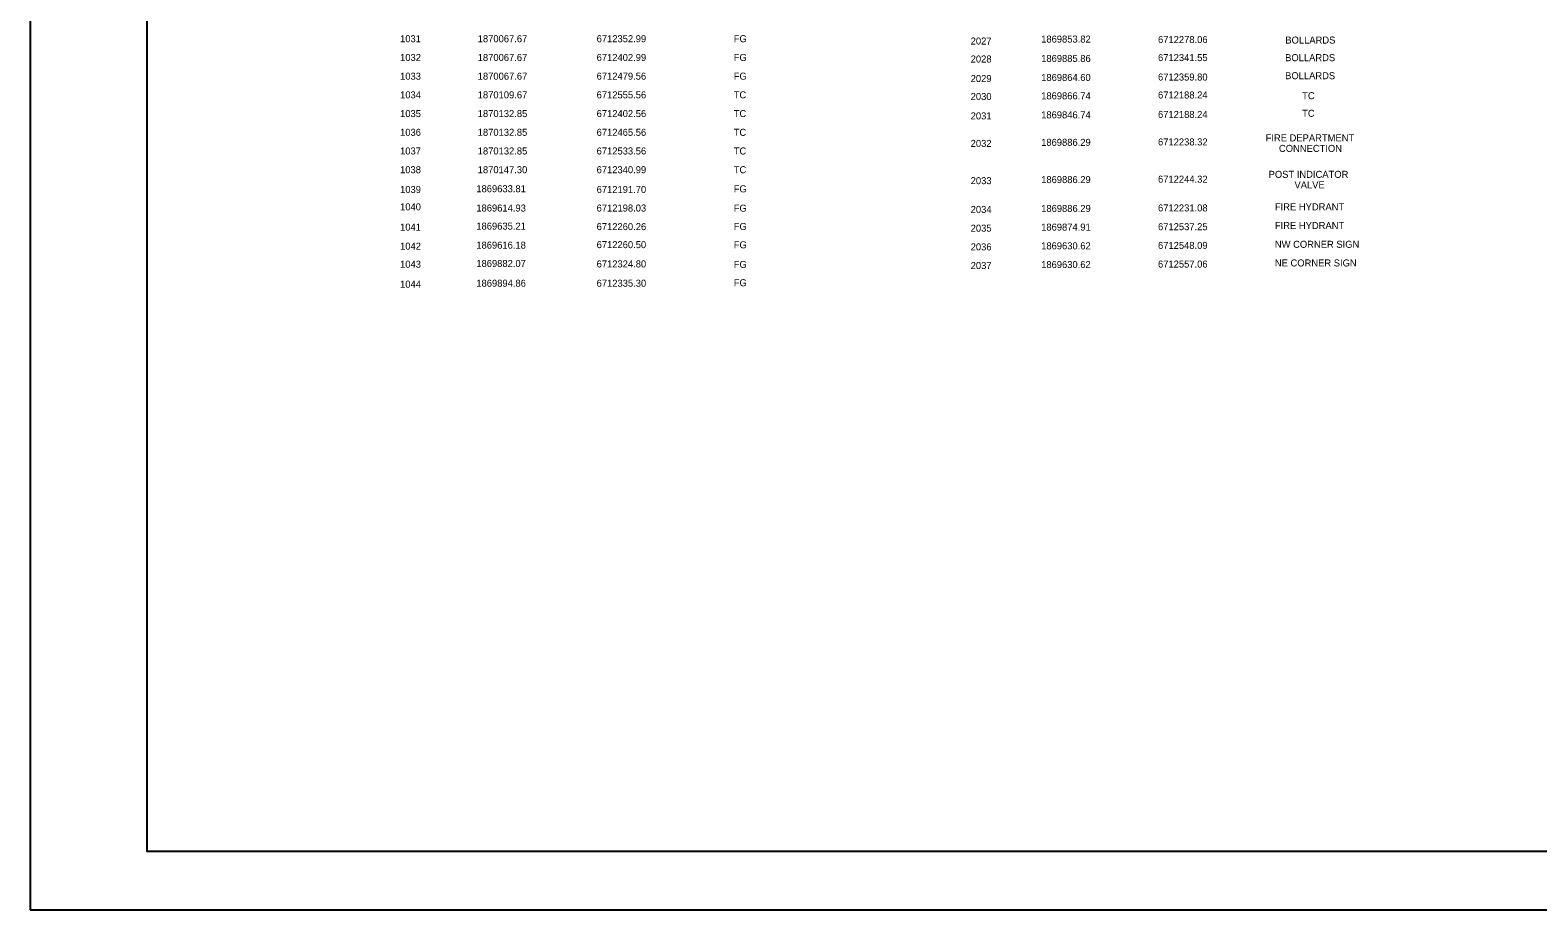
# Model space of a CAD drawing. Extents: x 0 to 4.36, y 0 to 2.5.
# Drawn here: x 0 to 2.15, y 0 to 1.254 of the extents above; entities that cross this region are included whole.
import ezdxf

# ---------------------------------------------------------------- set-up
doc = ezdxf.new("R2010")
doc.units = 0
for name, color, linetype in [('C-TEXT', 7, 'Continuous'), ('G-TTLB-OTLN', 7, 'Continuous'), ('G-TTLB-VIEW', 7, 'Continuous')]:
    doc.layers.add(name, color=color, linetype=linetype)

msp = doc.modelspace()

# ---------------------------------------------------------------- linework, layer by layer
at = {"layer": 'G-TTLB-OTLN'}
msp.add_lwpolyline([(0, 0), (3.5, 0), (3.5, 2.5), (0, 2.5)], close=True, dxfattribs=at)
at = {"layer": 'G-TTLB-VIEW'}
msp.add_lwpolyline([(0.1667, 2.4167), (3.0729, 2.4167), (3.0729, 0.0833), (0.1667, 0.0833)], close=True, dxfattribs=at)

# ---------------------------------------------------------------- texts
at = {"layer": 'C-TEXT'}
for s, p in [('1031', (0.5274, 1.2366)), ('1870067.67', (0.6381, 1.2366)), ('6712352.99', (0.8076, 1.2366)), ('FG', (1.0031, 1.2366)), ('2027', (1.3409, 1.2333)), ('1869853.82', (1.4414, 1.2361)), ('6712278.06', (1.608, 1.2354)), ('BOLLARDS', (1.7895, 1.2347)), ('1032', (0.5274, 1.2099)), ('1870067.67', (0.6381, 1.2099)), ('6712402.99', (0.8076, 1.2099)), ('FG', (1.0031, 1.2099)), ('2028', (1.3409, 1.2077)), ('1869885.86', (1.4414, 1.2085)), ('6712341.55', (1.608, 1.2097)), ('BOLLARDS', (1.7892, 1.2096)), ('1033', (0.5274, 1.1832)), ('1870067.67', (0.6381, 1.1832)), ('6712479.56', (0.8076, 1.1832)), ('FG', (1.0031, 1.1832)), ('2029', (1.3409, 1.1799)), ('1869864.60', (1.4414, 1.1814)), ('6712359.80', (1.608, 1.182)), ('BOLLARDS', (1.7892, 1.1839)), ('1034', (0.5274, 1.1566)), ('1870109.67', (0.6381, 1.1566)), ('6712555.56', (0.8076, 1.1566)), ('TC', (1.0031, 1.1566)), ('2030', (1.3409, 1.1543)), ('1869866.74', (1.4414, 1.1552)), ('6712188.24', (1.608, 1.1564)), ('TC', (1.8135, 1.1554)), ('1035', (0.5274, 1.1299)), ('1870132.85', (0.6381, 1.1299)), ('6712402.56', (0.8076, 1.1299)), ('TC', (1.0031, 1.1299)), ('TC', (1.8135, 1.1303)), ('2031', (1.3409, 1.1266)), ('1869846.74', (1.4414, 1.1281)), ('6712188.24', (1.608, 1.1287)), ('1036', (0.5274, 1.1032)), ('1870132.85', (0.6381, 1.1032)), ('6712465.56', (0.8076, 1.1032)), ('TC', (1.0031, 1.1032)), ('2032', (1.3409, 1.0874)), ('1869886.29', (1.4414, 1.0889)), ('6712238.32', (1.608, 1.0895)), ('FIRE DEPARTMENT', (1.7614, 1.0953)), ('1037', (0.5274, 1.0766)), ('1870132.85', (0.6381, 1.0766)), ('6712533.56', (0.8076, 1.0766)), ('TC', (1.0031, 1.0766)), ('CONNECTION', (1.7804, 1.0803)), ('1038', (0.5274, 1.0499)), ('1870147.30', (0.6381, 1.0499)), ('6712340.99', (0.8076, 1.0499)), ('TC', (1.0031, 1.0499)), ('POST INDICATOR', (1.7657, 1.0433)), ('1039', (0.5274, 1.0217)), ('1869633.81', (0.6361, 1.0228)), ('6712191.70', (0.8076, 1.0217)), ('FG', (1.0031, 1.0226)), ('2033', (1.3409, 1.0343)), ('1869886.29', (1.4414, 1.0358)), ('6712244.32', (1.608, 1.0364)), ('VALVE', (1.8025, 1.0283)), ('1040', (0.5274, 0.997)), ('1869614.93', (0.6361, 0.9953)), ('6712198.03', (0.8076, 0.9953)), ('FG', (1.0031, 0.9951)), ('2034', (1.3409, 0.9933)), ('1869886.29', (1.4414, 0.9947)), ('6712231.08', (1.608, 0.9954)), ('FIRE HYDRANT', (1.7746, 0.997)), ('1041', (0.5274, 0.9681)), ('1869635.21', (0.6361, 0.9695)), ('6712260.26', (0.8076, 0.9688)), ('FG', (1.0031, 0.969)), ('2035', (1.3409, 0.9666)), ('1869874.91', (1.4414, 0.9681)), ('6712537.25', (1.608, 0.9687)), ('FIRE HYDRANT', (1.7746, 0.9703)), ('1042', (0.5274, 0.941)), ('1869616.18', (0.6361, 0.9424)), ('6712260.50', (0.8076, 0.9431)), ('FG', (1.0031, 0.9429)), ('2036', (1.3409, 0.9399)), ('1869630.62', (1.4414, 0.9414)), ('6712548.09', (1.608, 0.942)), ('NW CORNER SIGN', (1.7746, 0.9436)), ('1043', (0.5274, 0.9152)), ('1869882.07', (0.6361, 0.9163)), ('6712324.80', (0.8076, 0.9156)), ('FG', (1.0031, 0.9149)), ('1869630.62', (1.4414, 0.9147)), ('6712557.06', (1.608, 0.9154)), ('NE CORNER SIGN', (1.7746, 0.917)), ('2037', (1.3409, 0.9133)), ('1044', (0.5274, 0.8867)), ('1869894.86', (0.6361, 0.8881)), ('6712335.30', (0.8076, 0.8881)), ('FG', (1.0031, 0.8888))]:
    msp.add_text(s, height=0.01, dxfattribs=at).set_placement(p)

doc.saveas('drawing.dxf')
